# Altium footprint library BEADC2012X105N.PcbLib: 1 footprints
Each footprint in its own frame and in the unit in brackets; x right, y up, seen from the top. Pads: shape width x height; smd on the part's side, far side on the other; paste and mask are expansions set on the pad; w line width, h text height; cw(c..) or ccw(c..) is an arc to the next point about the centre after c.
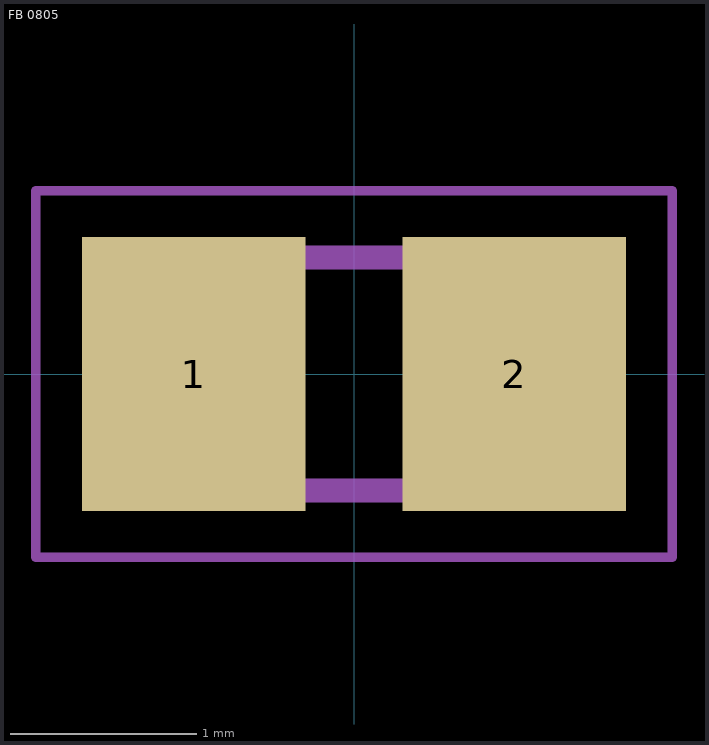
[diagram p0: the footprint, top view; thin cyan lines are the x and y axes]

## FB 0805 [mm] "BLM21AG331SN1D-Murata-Ferrite Beads Multi-Layer 330Ohm 25% 100MHz 0.8A 0.15Ohm DCR 0805 T/R"
pads (2):
  rect 1.2x1.47 smd: 1(-0.86,0) 2(0.86,0)
Mechanical 13:
  lines w0.127: -1,-0.625 1,-0.625 1,0.625 -1,0.625 -1,-0.625
Mechanical 15:
  lines w0.05: -1.708,-0.983 1.708,-0.983 1.708,0.983 -1.708,0.983 -1.708,-0.983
